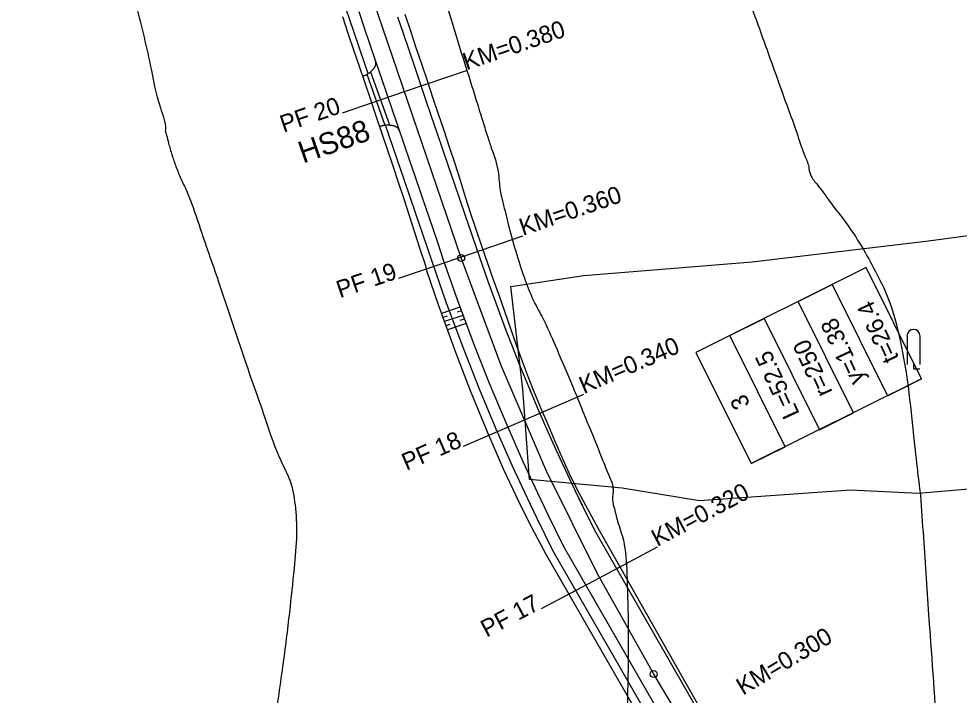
# Model space of a CAD drawing. Extents: x -478102 to -473059, y -1117705 to -1114104.
# Drawn here: x -476531.6 to -476424, y -1116940.4 to -1116863.1 of the extents above; entities that cross this region are included whole.
import ezdxf

# ---------------------------------------------------------------- set-up
doc = ezdxf.new("R2010")
doc.units = 0
for name, color, linetype in [('cestn___p____kop', 7, 'Continuous'), ('cesty', 7, 'Continuous'), ('HraniceSouvislehoPorostu', 7, 'Continuous'), ('POLYGONY_SITUACE_PF', 7, 'Continuous'), ('POLYGONY_SITUACE_PF_POPISY', 7, 'Continuous'), ('POLYGONY_SITUACE_PO', 7, 'Continuous'), ('popis', 7, 'Continuous'), ('PopisneZnackyKultura', 7, 'Continuous'), ('TABULKY', 7, 'Continuous'), ('TP_HS', 7, 'Continuous'), ('Vrstevnice_hlavni', 7, 'Continuous'), ('Vrstevnice_vedlejsi', 7, 'Continuous')]:
    doc.layers.add(name, color=color, linetype=linetype)

msp = doc.modelspace()

# ---------------------------------------------------------------- linework, layer by layer
at = {"layer": 'cestn___p____kop'}
for p, q in [((-476481.118, -1116896.094), (-476483.235, -1116896.8)), ((-476482.582, -1116897.109), (-476483.077, -1116897.274)), ((-476480.801, -1116897.042), (-476482.884, -1116897.737)), ((-476480.94, -1116896.504), (-476481.435, -1116896.669)), ((-476480.62, -1116897.451), (-476481.119, -1116897.618)), ((-476482.262, -1116898.057), (-476482.713, -1116898.207)), ((-476480.412, -1116897.967), (-476482.542, -1116898.677))]:
    msp.add_line(p, q, dxfattribs=at)
at = {"layer": 'cesty'}
for p, q in [((-476493.268, -1116864.576), (-476495.849, -1116857.004)), ((-476493.891, -1116864.788), (-476494.532, -1116862.894)), ((-476488.272, -1116862.873), (-476487.627, -1116864.766)), ((-476493.251, -1116866.683), (-476493.891, -1116864.788)), ((-476491.977, -1116868.362), (-476493.268, -1116864.576)), ((-476487.627, -1116864.766), (-476486.982, -1116866.659)), ((-476492.61, -1116868.578), (-476493.251, -1116866.683)), ((-476486.982, -1116866.659), (-476486.336, -1116868.552)), ((-476491.629, -1116869.384), (-476491.977, -1116868.362)), ((-476491.969, -1116870.472), (-476492.61, -1116868.578)), ((-476486.336, -1116868.552), (-476485.046, -1116872.338)), ((-476491.328, -1116872.367), (-476491.969, -1116870.472)), ((-476490.687, -1116874.261), (-476491.328, -1116872.367)), ((-476485.046, -1116872.338), (-476484.4, -1116874.231)), ((-476490.046, -1116876.156), (-476490.687, -1116874.261)), ((-476484.4, -1116874.231), (-476483.755, -1116876.124)), ((-476488.751, -1116877.827), (-476489.627, -1116875.258)), ((-476489.406, -1116878.05), (-476490.046, -1116876.156)), ((-476483.755, -1116876.124), (-476483.11, -1116878.017)), ((-476488.765, -1116879.945), (-476489.406, -1116878.05)), ((-476487.46, -1116881.613), (-476488.751, -1116877.827)), ((-476483.11, -1116878.017), (-476482.464, -1116879.91)), ((-476488.142, -1116881.846), (-476488.765, -1116879.945)), ((-476482.464, -1116879.91), (-476481.819, -1116881.803)), ((-476487.519, -1116883.746), (-476488.142, -1116881.846)), ((-476486.169, -1116885.399), (-476487.46, -1116881.613)), ((-476481.819, -1116881.803), (-476481.174, -1116883.696)), ((-476486.897, -1116885.647), (-476487.519, -1116883.746)), ((-476481.174, -1116883.696), (-476480.528, -1116885.589)), ((-476484.879, -1116889.185), (-476486.169, -1116885.399)), ((-476480.528, -1116885.589), (-476479.883, -1116887.482)), ((-476486.274, -1116887.548), (-476486.897, -1116885.647)), ((-476485.652, -1116889.449), (-476486.274, -1116887.548)), ((-476479.883, -1116887.482), (-476479.238, -1116889.375)), ((-476485.029, -1116891.35), (-476485.652, -1116889.449)), ((-476484.233, -1116891.078), (-476484.879, -1116889.185)), ((-476479.238, -1116889.375), (-476478.592, -1116891.255)), ((-476484.897, -1116891.914), (-476485.029, -1116891.35)), ((-476482.838, -1116891.211), (-476481.441, -1116895.193)), ((-476478.592, -1116891.255), (-476477.933, -1116893.126)), ((-476477.933, -1116893.126), (-476477.258, -1116894.992)), ((-476481.441, -1116895.193), (-476479.486, -1116900.437)), ((-476477.258, -1116894.992), (-476476.569, -1116896.853)), ((-476476.569, -1116896.853), (-476475.865, -1116898.708)), ((-476475.865, -1116898.708), (-476475.147, -1116900.557)), ((-476479.486, -1116900.437), (-476477.767, -1116904.776)), ((-476475.147, -1116900.557), (-476474.413, -1116902.4)), ((-476474.413, -1116902.4), (-476473.665, -1116904.238)), ((-476477.767, -1116904.776), (-476475.775, -1116909.531)), ((-476473.665, -1116904.238), (-476472.902, -1116906.069)), ((-476472.902, -1116906.069), (-476472.124, -1116907.895)), ((-476472.124, -1116907.895), (-476471.332, -1116909.714)), ((-476475.775, -1116909.531), (-476473.924, -1116913.719)), ((-476471.332, -1116909.714), (-476470.526, -1116911.526)), ((-476470.526, -1116911.526), (-476469.705, -1116913.332)), ((-476469.705, -1116913.332), (-476468.869, -1116915.132)), ((-476473.924, -1116913.719), (-476472.266, -1116917.307)), ((-476468.869, -1116915.132), (-476468.019, -1116916.924)), ((-476472.266, -1116917.307), (-476471.125, -1116919.694)), ((-476468.019, -1116916.924), (-476467.155, -1116918.71)), ((-476467.525, -1116917.949), (-476465.729, -1116921.579)), ((-476471.125, -1116919.694), (-476469.3, -1116923.382)), ((-476465.729, -1116921.579), (-476447.484, -1116953.329)), ((-476452.624, -1116954.978), (-476470.453, -1116923.964))]:
    msp.add_line(p, q, dxfattribs=at)
for points in [[(-476492.704, -1116862.271), (-476492.058, -1116864.164)], [(-476487.426, -1116862.584), (-476486.79, -1116864.481)], [(-476492.058, -1116864.164), (-476491.413, -1116866.057)], [(-476486.79, -1116864.481), (-476486.155, -1116866.377)], [(-476491.413, -1116866.057), (-476490.768, -1116867.95)], [(-476486.155, -1116866.377), (-476485.519, -1116868.273)], [(-476490.768, -1116867.95), (-476490.122, -1116869.843)], [(-476485.519, -1116868.273), (-476484.884, -1116870.17)], [(-476490.122, -1116869.843), (-476489.477, -1116871.736)], [(-476484.884, -1116870.17), (-476484.248, -1116872.066)], [(-476489.477, -1116871.736), (-476488.832, -1116873.629)], [(-476484.248, -1116872.066), (-476483.613, -1116873.963)], [(-476488.832, -1116873.629), (-476488.186, -1116875.522)], [(-476483.613, -1116873.963), (-476482.977, -1116875.859)], [(-476488.186, -1116875.522), (-476487.541, -1116877.415)], [(-476482.977, -1116875.859), (-476482.342, -1116877.755)], [(-476487.541, -1116877.415), (-476486.896, -1116879.308)], [(-476482.342, -1116877.755), (-476481.707, -1116879.652)], [(-476486.896, -1116879.308), (-476486.25, -1116881.201)], [(-476481.707, -1116879.652), (-476481.104, -1116881.559)], [(-476486.25, -1116881.201), (-476485.605, -1116883.094)], [(-476481.104, -1116881.559), (-476480.509, -1116883.47)], [(-476485.605, -1116883.094), (-476484.96, -1116884.987)], [(-476480.509, -1116883.47), (-476479.907, -1116885.378)], [(-476484.96, -1116884.987), (-476484.314, -1116886.88)], [(-476479.907, -1116885.378), (-476479.267, -1116887.272)], [(-476484.314, -1116886.88), (-476483.669, -1116888.773)], [(-476479.267, -1116887.272), (-476478.626, -1116889.167)], [(-476483.669, -1116888.773), (-476483.024, -1116890.666)], [(-476478.626, -1116889.167), (-476477.985, -1116891.044)], [(-476483.024, -1116890.666), (-476482.838, -1116891.211)], [(-476483.536, -1116895.947), (-476484.897, -1116891.914)], [(-476482.656, -1116895.631), (-476484.233, -1116891.078)], [(-476477.985, -1116891.044), (-476477.329, -1116892.911)], [(-476477.329, -1116892.911), (-476476.654, -1116894.771)], [(-476476.654, -1116894.771), (-476476.006, -1116896.642)], [(-476481.604, -1116901.253), (-476483.536, -1116895.947)], [(-476480.691, -1116900.901), (-476482.656, -1116895.631)], [(-476476.006, -1116896.642), (-476475.358, -1116898.513)], [(-476475.358, -1116898.513), (-476474.693, -1116900.378)], [(-476474.693, -1116900.378), (-476474.013, -1116902.239)], [(-476479.902, -1116905.645), (-476481.604, -1116901.253)], [(-476478.963, -1116905.263), (-476480.691, -1116900.901)], [(-476474.013, -1116902.239), (-476473.318, -1116904.095)], [(-476473.318, -1116904.095), (-476472.577, -1116905.932)], [(-476477.923, -1116910.457), (-476479.902, -1116905.645)], [(-476476.961, -1116910.042), (-476478.963, -1116905.263)], [(-476472.577, -1116905.932), (-476471.818, -1116907.762)], [(-476471.818, -1116907.762), (-476471.041, -1116909.585)], [(-476475.101, -1116914.252), (-476476.961, -1116910.042)], [(-476471.041, -1116909.585), (-476470.256, -1116911.405)], [(-476476.084, -1116914.697), (-476477.923, -1116910.457)], [(-476470.256, -1116911.405), (-476469.459, -1116913.22)], [(-476469.459, -1116913.22), (-476468.659, -1116915.033)], [(-476473.434, -1116917.858), (-476475.101, -1116914.252)], [(-476474.39, -1116918.309), (-476476.084, -1116914.697)], [(-476468.659, -1116915.033), (-476467.805, -1116916.822)], [(-476472.287, -1116920.257), (-476473.434, -1116917.858)], [(-476467.805, -1116916.822), (-476466.846, -1116918.559)], [(-476467.257, -1116917.819), (-476465.33, -1116921.377)], [(-476473.185, -1116920.693), (-476474.39, -1116918.309)], [(-476471.258, -1116924.37), (-476473.185, -1116920.693)], [(-476470.453, -1116923.964), (-476472.287, -1116920.257)], [(-476465.33, -1116921.377), (-476447.268, -1116953.2), (-476401.549, -1117029.226)], [(-476469.3, -1116923.382), (-476450.918, -1116955.381), (-476400.592, -1117039.597)], [(-476402.179, -1117040.546), (-476452.76, -1116956.482), (-476471.258, -1116924.37)]]:
    msp.add_lwpolyline(points, dxfattribs=at)
at = {"layer": 'HraniceSouvislehoPorostu'}
msp.add_lwpolyline([(-476406.997, -1116915.503), (-476428.657, -1116917.398), (-476436.466, -1116917.015), (-476453.731, -1116918.234), (-476462.564, -1116916.788), (-476473.178, -1116915.786), (-476473.946, -1116905.453), (-476475.287, -1116893.736), (-476466.965, -1116892.471), (-476447.716, -1116890.91), (-476427.538, -1116888.513), (-476414.781, -1116886.795)], dxfattribs=at)
at = {"layer": 'POLYGONY_SITUACE_PF'}
for points in [[(-476494.567, -1116873.851), (-476487.468, -1116871.431), (-476480.369, -1116869.011)], [(-476488.116, -1116892.773), (-476481.018, -1116890.353), (-476473.919, -1116887.933)], [(-476480.708, -1116911.98), (-476473.824, -1116909.003), (-476466.94, -1116906.027)], [(-476471.788, -1116930.536), (-476465.164, -1116927.019), (-476458.54, -1116923.502)]]:
    msp.add_lwpolyline(points, dxfattribs=at)
at = {"layer": 'POLYGONY_SITUACE_PO'}
msp.add_lwpolyline([(-476301.427, -1117045.065), (-476372.905, -1117052.019), (-476378.974, -1117051.908), (-476382.069, -1117051.436), (-476384.865, -1117050.444), (-476390.281, -1117047.7), (-476394.946, -1117043.817), (-476398.626, -1117038.989), (-476458.957, -1116938.029), (-476465.394, -1116926.586), (-476471.221, -1116914.82), (-476476.422, -1116902.765), (-476480.983, -1116890.454), (-476499.392, -1116836.452), (-476499.929, -1116834.228), (-476500.052, -1116831.944), (-476499.756, -1116829.676), (-476499.052, -1116827.5), (-476496.647, -1116821.88)], dxfattribs=at)
for centre in [(-476480.983, -1116890.454), (-476458.957, -1116938.029)]:
    msp.add_circle(centre, 0.395, dxfattribs=at)
at = {"layer": 'PopisneZnackyKultura'}
for p, q in [((-476429.985, -1116899.372), (-476429.985, -1116902.632)), ((-476428.505, -1116899.372), (-476428.505, -1116902.632))]:
    msp.add_line(p, q, dxfattribs=at)
msp.add_lwpolyline([(-476429.245, -1116902.632), (-476429.245, -1116903.132), (-476428.505, -1116903.132)], dxfattribs=at)
msp.add_arc((-476429.246, -1116899.381), 0.75, 0, 180, dxfattribs=at)
at = {"layer": 'TABULKY'}
msp.add_lwpolyline([(-476428.325, -1116904.282), (-476447.828, -1116913.976), (-476443.931, -1116912.039), (-476450.254, -1116899.318), (-476446.339, -1116897.372), (-476440.016, -1116910.093), (-476436.119, -1116908.156), (-476442.442, -1116895.435), (-476438.545, -1116893.498), (-476432.222, -1116906.219), (-476428.325, -1116904.282), (-476434.647, -1116891.561), (-476454.142, -1116901.251), (-476447.828, -1116913.976)], dxfattribs=at)
at = {"layer": 'TP_HS'}
for p, q in [((-476491.761, -1116869.463), (-476489.713, -1116875.267)), ((-476491.334, -1116869.169), (-476489.188, -1116875.25))]:
    msp.add_line(p, q, dxfattribs=at)
for points in [[(-476492.218, -1116869.684), (-476492.13, -1116869.645), (-476491.99, -1116869.579), (-476491.85, -1116869.51), (-476491.737, -1116869.45), (-476491.628, -1116869.383), (-476491.522, -1116869.312), (-476491.47, -1116869.274), (-476491.418, -1116869.236), (-476491.29, -1116869.131), (-476491.172, -1116869.018), (-476491.06, -1116868.897), (-476491.006, -1116868.834), (-476490.952, -1116868.769), (-476490.896, -1116868.696), (-476490.846, -1116868.62), (-476490.804, -1116868.539), (-476490.786, -1116868.497), (-476490.771, -1116868.452), (-476490.752, -1116868.384), (-476490.746, -1116868.349), (-476490.741, -1116868.314), (-476490.737, -1116868.245), (-476490.74, -1116868.176), (-476490.768, -1116867.95)], [(-476490.307, -1116875.396), (-476490.223, -1116875.374), (-476490.072, -1116875.337), (-476489.997, -1116875.32), (-476489.921, -1116875.303), (-476489.795, -1116875.279), (-476489.668, -1116875.262), (-476489.541, -1116875.251), (-476489.477, -1116875.248), (-476489.412, -1116875.245), (-476489.246, -1116875.247), (-476489.083, -1116875.26), (-476488.921, -1116875.284), (-476488.839, -1116875.299), (-476488.756, -1116875.316), (-476488.666, -1116875.338), (-476488.58, -1116875.366), (-476488.497, -1116875.402), (-476488.456, -1116875.424), (-476488.416, -1116875.449), (-476488.359, -1116875.49), (-476488.332, -1116875.513), (-476488.306, -1116875.537), (-476488.282, -1116875.562), (-476488.26, -1116875.588), (-476488.219, -1116875.644), (-476488.099, -1116875.838)]]:
    msp.add_spline(points, degree=3, dxfattribs=at)
at = {"layer": 'Vrstevnice_hlavni'}
msp.add_spline([(-476493.715, -1116836.779), (-476493.657, -1116837.782), (-476493.454, -1116838.814), (-476493.106, -1116839.874), (-476492.613, -1116840.964), (-476491.914, -1116842.563), (-476491.008, -1116844.672), (-476489.895, -1116847.291), (-476489.121, -1116849.068), (-476488.687, -1116850.006), (-476488.591, -1116850.102), (-476488.194, -1116850.666), (-476487.494, -1116851.699), (-476486.491, -1116853.199), (-476485.812, -1116854.196), (-476485.456, -1116854.691), (-476485.422, -1116854.683), (-476485.307, -1116854.78), (-476485.109, -1116854.984), (-476484.829, -1116855.293), (-476484.118, -1116857.163), (-476482.975, -1116860.594), (-476481.402, -1116865.585), (-476480.12, -1116869.665), (-476479.13, -1116872.833), (-476478.431, -1116875.088), (-476477.86, -1116876.887), (-476477.416, -1116878.229), (-476477.099, -1116879.115), (-476476.855, -1116880.078), (-476476.685, -1116881.12), (-476476.587, -1116882.239), (-476476.21, -1116884.112), (-476475.555, -1116886.737), (-476474.62, -1116890.115), (-476473.657, -1116893.01), (-476472.666, -1116895.422), (-476471.647, -1116897.352), (-476470.243, -1116900.412), (-476468.455, -1116904.603), (-476466.283, -1116909.925), (-476464.77, -1116913.634), (-476463.916, -1116915.731), (-476463.721, -1116916.214), (-476463.617, -1116916.722), (-476463.603, -1116917.256), (-476463.679, -1116917.815), (-476463.509, -1116918.911), (-476463.093, -1116920.547), (-476462.43, -1116922.72), (-476462.028, -1116926.548), (-476461.886, -1116932.03), (-476462.123, -1116946.304)], degree=3, dxfattribs=at)
at = {"layer": 'Vrstevnice_vedlejsi'}
for points in [[(-476571.958, -1116704.162), (-476571.904, -1116704.215), (-476571.688, -1116704.429), (-476571.311, -1116704.803), (-476570.773, -1116705.338), (-476569.946, -1116706.363), (-476568.83, -1116707.879), (-476567.427, -1116709.886), (-476566.203, -1116711.628), (-476565.16, -1116713.105), (-476564.298, -1116714.317), (-476563.772, -1116715.225), (-476563.581, -1116715.829), (-476563.726, -1116716.129), (-476564.073, -1116716.669), (-476564.621, -1116717.45), (-476565.371, -1116718.471), (-476565.697, -1116719.715), (-476565.599, -1116721.18), (-476565.077, -1116722.867), (-476563.322, -1116725.926), (-476560.334, -1116730.356), (-476556.114, -1116736.158), (-476552.562, -1116741.631), (-476549.677, -1116746.776), (-476547.46, -1116751.593), (-476545.693, -1116756.042), (-476544.374, -1116760.122), (-476543.504, -1116763.833), (-476542.206, -1116769.314), (-476540.482, -1116776.566), (-476538.329, -1116785.587), (-476536.736, -1116792.746), (-476535.702, -1116798.044), (-476535.228, -1116801.481), (-476533.66, -1116807.541), (-476530.999, -1116816.224), (-476527.246, -1116827.53), (-476524.726, -1116835.32), (-476523.44, -1116839.595), (-476523.389, -1116840.354), (-476523.331, -1116841.083), (-476523.266, -1116841.783), (-476523.195, -1116842.453), (-476522.8, -1116844.094), (-476522.082, -1116846.705), (-476521.041, -1116850.288), (-476519.77, -1116855.097), (-476518.27, -1116861.134), (-476516.539, -1116868.399), (-476515.387, -1116873.283), (-476514.813, -1116875.785), (-476514.818, -1116875.907), (-476514.695, -1116876.43), (-476514.444, -1116877.353), (-476514.064, -1116878.676), (-476513.598, -1116880.016), (-476513.045, -1116881.373), (-476512.404, -1116882.746), (-476510.965, -1116886.684), (-476508.726, -1116893.188), (-476505.69, -1116902.257), (-476503.32, -1116909.062), (-476501.617, -1116913.604), (-476500.581, -1116915.881), (-476499.982, -1116918.695), (-476499.82, -1116922.044), (-476500.095, -1116925.93), (-476500.622, -1116930.955), (-476501.399, -1116937.119), (-476502.428, -1116944.424), (-476503.284, -1116951.043), (-476503.968, -1116956.977), (-476504.479, -1116962.226), (-476505.481, -1116968.833), (-476506.974, -1116976.798), (-476508.959, -1116986.121), (-476510.49, -1116993.241), (-476511.568, -1116998.159), (-476512.192, -1117000.873), (-476513.406, -1117005.693), (-476515.21, -1117012.619), (-476517.605, -1117021.651), (-476519.543, -1117028.708), (-476521.025, -1117033.789), (-476522.05, -1117036.895), (-476522.813, -1117039.387), (-476523.316, -1117041.266), (-476523.557, -1117042.532), (-476525.061, -1117047.398), (-476527.83, -1117055.865), (-476531.861, -1117067.933), (-476534.429, -1117077.623), (-476535.532, -1117084.937), (-476535.172, -1117089.874), (-476535.368, -1117095.964), (-476536.121, -1117103.207)], [(-476429.382, -1116802.255), (-476427.577, -1116804.493), (-476426.152, -1116806.848), (-476425.107, -1116809.32), (-476424.442, -1116811.91), (-476423.987, -1116813.812), (-476423.744, -1116815.028), (-476423.711, -1116815.556), (-476423.685, -1116815.983), (-476423.665, -1116816.309), (-476423.653, -1116816.533), (-476423.365, -1116819.955), (-476422.802, -1116826.574), (-476421.964, -1116836.392), (-476420.828, -1116844.21), (-476419.393, -1116850.028), (-476417.658, -1116853.847), (-476415.4, -1116859.181), (-476412.617, -1116866.03), (-476409.309, -1116874.395), (-476407.176, -1116880.263), (-476406.218, -1116883.637), (-476406.434, -1116884.515), (-476405.944, -1116887.374), (-476404.748, -1116892.215), (-476402.846, -1116899.038), (-476401.243, -1116903.921), (-476399.938, -1116906.863), (-476398.934, -1116907.866), (-476397.275, -1116909.125), (-476394.963, -1116910.641), (-476391.996, -1116912.413), (-476390.213, -1116913.967), (-476389.611, -1116915.304), (-476390.193, -1116916.422), (-476390.887, -1116917.801), (-476391.694, -1116919.438), (-476392.614, -1116921.336), (-476393.031, -1116926.229), (-476392.946, -1116934.117), (-476392.357, -1116945.001), (-476391.819, -1116953.244), (-476391.329, -1116958.848), (-476390.889, -1116961.812), (-476390.846, -1116967.295), (-476391.198, -1116975.299), (-476391.947, -1116985.824), (-476392.181, -1116993.785), (-476391.901, -1116999.183), (-476391.105, -1117002.017), (-476389.811, -1117006.894), (-476388.017, -1117013.813), (-476385.723, -1117022.773), (-476384.311, -1117030.528), (-476383.779, -1117037.076), (-476384.129, -1117042.418), (-476384.841, -1117048.939), (-476385.915, -1117056.638), (-476387.35, -1117065.515), (-476388.856, -1117072.405), (-476390.432, -1117077.308), (-476392.079, -1117080.223), (-476393.566, -1117082.614), (-476394.896, -1117084.483), (-476396.066, -1117085.828), (-476397.154, -1117086.924), (-476398.158, -1117087.772), (-476399.079, -1117088.372), (-476401.752, -1117090.16), (-476406.178, -1117093.136), (-476412.357, -1117097.3), (-476418.052, -1117102.136), (-476423.265, -1117107.643), (-476427.995, -1117113.822), (-476432.008, -1117118.372), (-476435.302, -1117121.295), (-476437.878, -1117122.589), (-476440.56, -1117123.926), (-476443.35, -1117125.307), (-476446.245, -1117126.73), (-476448.454, -1117128.002), (-476449.974, -1117129.124), (-476450.808, -1117130.096), (-476452.012, -1117133.139), (-476453.587, -1117138.255), (-476455.534, -1117145.443), (-476456.4, -1117152.564), (-476456.185, -1117159.618), (-476454.889, -1117166.606), (-476452.79, -1117171.269), (-476449.889, -1117173.608), (-476446.185, -1117173.624), (-476443.257, -1117173.694), (-476441.107, -1117173.819), (-476439.733, -1117173.999), (-476438.562, -1117174.121), (-476437.593, -1117174.185)], [(-476452.85, -1116834.766), (-476452.763, -1116836.45), (-476452.562, -1116837.981), (-476452.248, -1116839.358), (-476451.821, -1116840.582), (-476451.441, -1116841.599), (-476451.108, -1116842.409), (-476450.824, -1116843.01), (-476450.631, -1116843.458), (-476450.53, -1116843.75), (-476450.521, -1116843.889), (-476450.642, -1116844.019), (-476450.893, -1116844.142), (-476451.274, -1116844.257), (-476451.636, -1116844.362), (-476451.98, -1116844.456), (-476452.305, -1116844.54), (-476452.489, -1116844.891), (-476452.534, -1116845.508), (-476452.439, -1116846.393), (-476452.377, -1116847.124), (-476452.349, -1116847.701), (-476452.354, -1116848.126), (-476452.334, -1116848.53), (-476452.288, -1116848.914), (-476452.216, -1116849.278), (-476451.375, -1116851.721), (-476449.763, -1116856.244), (-476447.382, -1116862.847), (-476445.375, -1116868.421), (-476443.743, -1116872.966), (-476442.485, -1116876.483), (-476441.641, -1116878.888), (-476441.211, -1116880.182), (-476441.195, -1116880.364), (-476441.153, -1116880.565), (-476441.084, -1116880.785), (-476440.99, -1116881.025), (-476440.244, -1116882.086), (-476438.849, -1116883.967), (-476436.803, -1116886.669), (-476434.982, -1116889.477), (-476433.386, -1116892.391), (-476432.015, -1116895.411), (-476430.876, -1116899.416), (-476429.969, -1116904.405), (-476429.293, -1116910.379), (-476428.831, -1116914.444), (-476428.585, -1116916.601), (-476428.553, -1116916.85), (-476428.523, -1116917.047), (-476428.494, -1116917.192), (-476428.467, -1116917.285), (-476428.451, -1116917.352), (-476428.447, -1116917.391), (-476428.453, -1116917.404), (-476428.455, -1116917.446), (-476428.452, -1116917.518), (-476428.446, -1116917.62), (-476428.12, -1116922.385), (-476427.475, -1116931.814), (-476426.511, -1116945.907), (-476425.976, -1116956.8), (-476425.87, -1116964.494), (-476426.194, -1116968.988), (-476426.432, -1116974.931), (-476426.584, -1116982.322), (-476426.65, -1116991.161), (-476427.252, -1117000.578), (-476428.388, -1117010.572), (-476430.059, -1117021.144), (-476430.881, -1117029.111), (-476430.854, -1117034.474), (-476429.978, -1117037.232), (-476429.977, -1117042.889), (-476430.852, -1117051.444), (-476432.602, -1117062.898), (-476433.9, -1117071.162), (-476434.745, -1117076.235), (-476435.138, -1117078.117), (-476435.697, -1117079.572), (-476436.421, -1117080.6), (-476437.311, -1117081.2), (-476438.104, -1117081.861), (-476438.8, -1117082.583), (-476439.4, -1117083.366), (-476442.225, -1117086.66), (-476447.274, -1117092.463), (-476454.548, -1117100.776), (-476460.096, -1117107.53), (-476463.917, -1117112.726), (-476466.012, -1117116.363), (-476467.87, -1117119.015), (-476469.493, -1117120.681), (-476470.879, -1117121.362), (-476472.889, -1117123.083), (-476475.524, -1117125.843)]]:
    msp.add_spline(points, degree=3, dxfattribs=at)

# ---------------------------------------------------------------- texts
for s, height, p in [('t=26.4', 1.9765, (-476430.866, -1116901.908)), ('y=1.38', 1.9765, (-476434.79, -1116904.395)), ('r=250', 1.9765, (-476438.464, -1116905.771)), ('L=52.5', 1.9765, (-476442.23, -1116908.272)), ('3', 1.976, (-476447.892, -1116907.213))]:
    msp.add_text(s, height=height, rotation=114.84279).set_placement(p)
at = {"layer": 'POLYGONY_SITUACE_PF_POPISY'}
for s, rotation, p in [('KM=0.380', 18.82411, (-476480.381, -1116869.015)), ('PF 20', 18.82411, (-476501.301, -1116876.147)), ('KM=0.360', 18.82411, (-476473.93, -1116887.937)), ('PF 19', 18.82411, (-476494.851, -1116895.068)), ('KM=0.340', 23.38209, (-476466.952, -1116906.032)), ('PF 18', 23.38209, (-476487.239, -1116914.803)), ('KM=0.320', 27.96452, (-476458.551, -1116923.508)), ('PF 17', 27.96452, (-476478.073, -1116933.872)), ('KM=0.300', 30.86147, (-476448.754, -1116940.506))]:
    msp.add_text(s, height=1.9765, rotation=rotation, dxfattribs=at).set_placement(p)
at = {"layer": 'popis'}
msp.add_text('HS88', height=2.5, rotation=19.26222, dxfattribs=at).set_placement((-476499.075, -1116879.664))

doc.saveas('drawing.dxf')
